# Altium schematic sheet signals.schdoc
size 289 x 193 mm
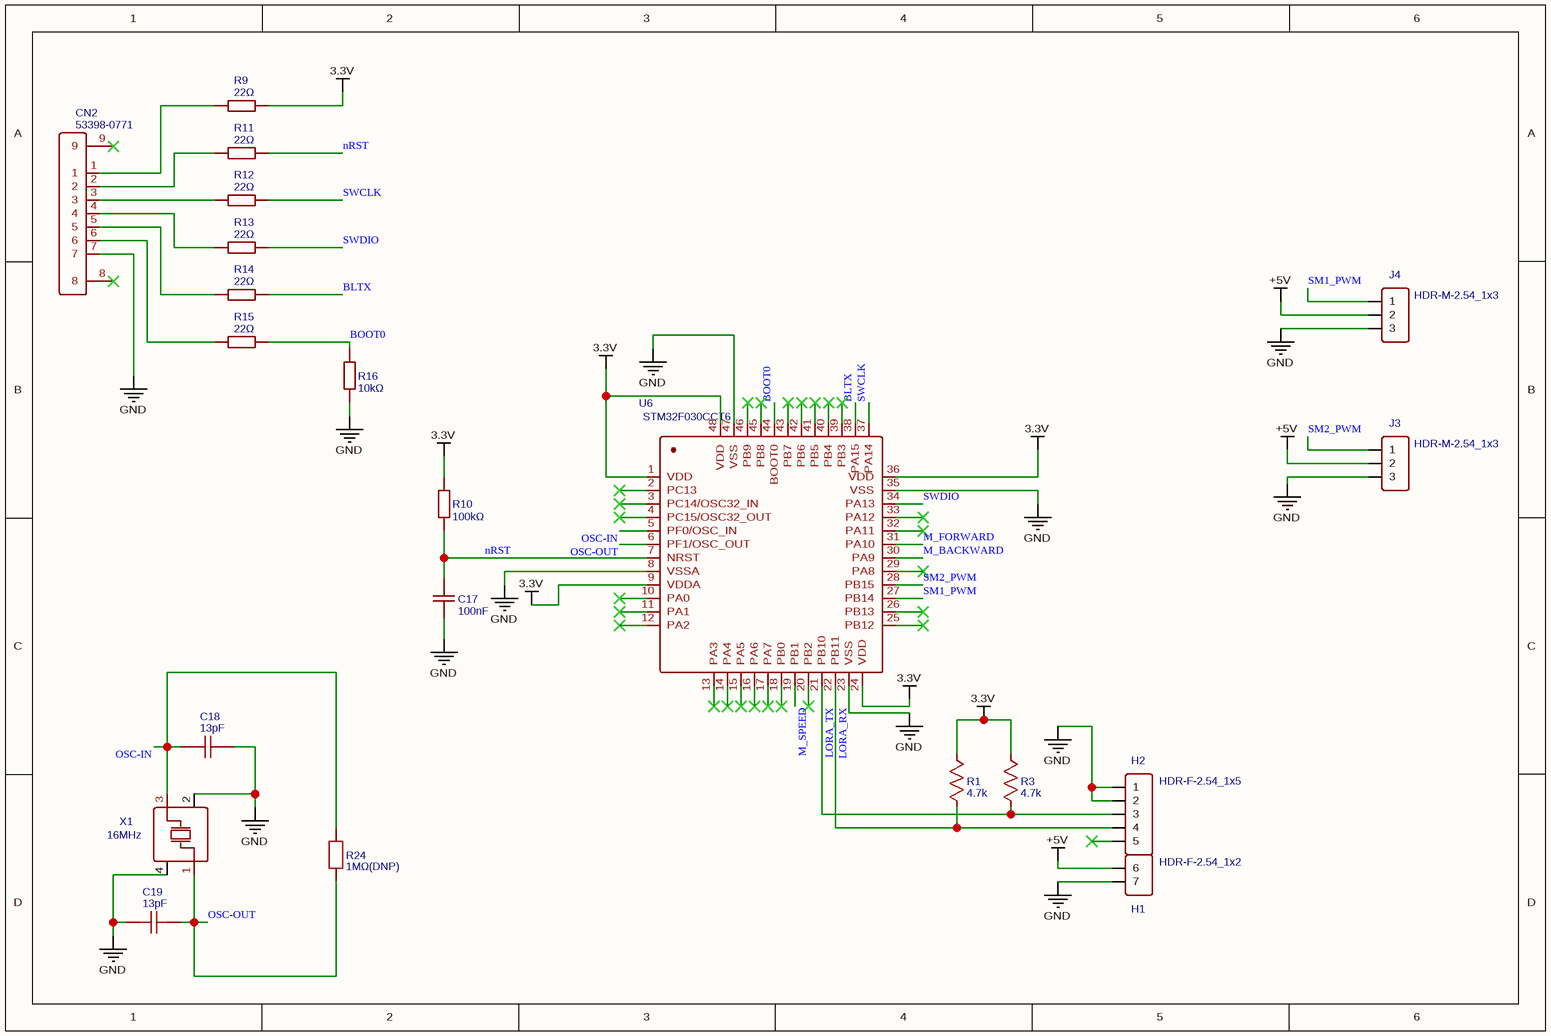
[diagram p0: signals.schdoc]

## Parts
C17  100nF  [C1206]
C18  13pF  [C0402]
C19  13pF  [C0402]
CN2  53398-0771  [CONN-SMD_7P-P1.25_53398-0771]
H1  HDR-F-2.54_1x2  [HDR-F-2.54_1X2]
H2  HDR-F-2.54_1x5  [HDR-F-2.54_1X5]
J3  HDR-M-2.54_1x3  [HDR-M-2.54_1X3]
J4  HDR-M-2.54_1x3  [HDR-M-2.54_1X3]
R1  4.7k  [R0805]
R3  4.7k  [R0805]
R9  22Ω  [R0805]
R10  100kΩ  [R0603]
R11  22Ω  [R0805]
R12  22Ω  [R0805]
R13  22Ω  [R0805]
R14  22Ω  [R0805]
R15  22Ω  [R0805]
R16  10kΩ  [R0603]
R24  1MΩ(DNP)  [R0805]
U6  STM32F030CCT6  [LQFP-48_L7.0-W7.0-P0.50-LS9.0-BL]
X1  16MHz  [CRYSTAL-SMD_4P-L3.2-W2.5-BL]

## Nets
3.3V: R1.1 R3.1 R9.2 R10.1 U6.1(VDD) U6.9(VDDA) U6.24(VDD) U6.36(VDD) U6.48(VDD)
+5V: H1.1(6) J3.2 J4.2
GND: C17.1 C18.2 C19.1 CN2.7 H1.2(7) H2.1 H2.2 J3.3 J4.3 R16.1 U6.8(VSSA) U6.23(VSS) U6.35(VSS) U6.47(VSS) X1.2(GND) X1.4(GND)
BLTX: R14.2 U6.38(PA15)
BOOT0: R15.2 R16.2 U6.44(BOOT0)
LORA_RX: H2.4 R1.2 U6.22(PB11)
LORA_TX: H2.3 R3.2 U6.21(PB10)
M_BACKWARD: U6.30(PA9)
M_FORWARD: U6.31(PA10)
M_SPEED: U6.19(PB1)
nRST: C17.2 R10.2 R11.2 U6.7(NRST)
OSC-IN: C18.1 R24.2 U6.5(PF0/OSC_IN) X1.3(OSC2)
OSC-OUT: C19.2 R24.1 U6.6(PF1/OSC_OUT) X1.1(OSC1)
SM1_PWM: J4.1 U6.27(PB14)
SM2_PWM: J3.1 U6.28(PB15)
SWCLK: R12.2 U6.37(PA14)
SWDIO: R13.2 U6.34(PA13)
NetCN2_1: CN2.1 R9.1
NetCN2_2: CN2.2 R11.1
NetCN2_3: CN2.3 R12.1
NetCN2_4: CN2.4 R13.1
NetCN2_5: CN2.5 R14.1
NetCN2_6: CN2.6 R15.1

Not connected (* = marked no-connect by the designer): CN2 8* 9*; H2 5*; U6 2(PC13)* 3(PC14/OSC32_IN)* 4(PC15/OSC32_OUT)* 10(PA0)* 11(PA1)* 12(PA2)* 13(PA3)* 14(PA4)* 15(PA5)* 16(PA6)* 17(PA7)* 18(PB0)* 20(PB2)* 25(PB12)* 26(PB13)* 29(PA8)* 32(PA11)* 33(PA12)* 39(PB3)* 40(PB4)* 41(PB5)* 42(PB6)* 43(PB7)* 45(PB8)* 46(PB9)*

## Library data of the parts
C17 = 100nF: Manufacturer Part: CL31B104KBCNNNC; Manufacturer: SAMSUNG(三星); nameAlias: Value
C18 C19 = 13pF: Manufacturer: YAGEO(国巨); Manufacturer Part: CC0402FRNPO9BN130; nameAlias: Value; Contributor: LCSC
CN2 = 53398-0771: Manufacturer: MOLEX; Manufacturer Part: 533980771; Contributor: LCSC
H1 = HDR-F-2.54_1x2: Contributor: LCEDA_Lib
H2 = HDR-F-2.54_1x5: Contributor: LCEDA_Lib
J3 J4 = HDR-M-2.54_1x3: Contributor: LCEDA_Lib
R1 R3 = 4.7k: nameAlias: Value(Ω); Contributor: LCEDA_Lib
R9 R11-R15 = 22Ω: Manufacturer: UNI-ROYAL(厚声); Manufacturer Part: 0805W8F220JT5E; nameAlias: Value
R10 = 100kΩ: Manufacturer: UNI-ROYAL(厚声); Manufacturer Part: 0603WAF1003T5E; nameAlias: Value
R16 = 10kΩ: Manufacturer: UNI-ROYAL(厚声); Manufacturer Part: 0603WAF1002T5E; nameAlias: Value
R24 = 1MΩ(DNP): Manufacturer: Viking(光颉); Manufacturer Part: AR05BTC1004; nameAlias: Value; Contributor: LCSC
U6 = STM32F030CCT6: Manufacturer: ST(意法半导体)
X1 = 16MHz: Manufacturer: TAE(雅晶鑫); Manufacturer Part: TAXM16M4RDBCCT2T; nameAlias: Value; Contributor: LCSC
